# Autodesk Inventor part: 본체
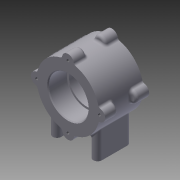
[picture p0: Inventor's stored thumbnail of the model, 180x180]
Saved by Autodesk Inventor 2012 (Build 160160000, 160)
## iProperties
Created: 2015-03
Part Number: 본체
Material: 알루미늄-6061
Document SubType Name: Modeling
Designer: Owner
Density: 2.71 g/cm^3
Mass: 450.772 g
Surface Area: 332.692 cm^2
Volume: 166.337 cm^3
Author: Owner
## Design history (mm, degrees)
sketch "스케치1"
  geometry: C1 r 37 at (0, 0); 1 further point
  constraints: 1 centre point, 1 coincident
  dimensions: "d0" = 74 diameter of C1
extrude "돌출1" new body sketch "스케치1" stored distance "d1" = 52; taper "d2" = 0 deg
sketch "스케치2"
  geometry: L1 (-37, 26)-(37, 26) reference; L2 (37, -26)-(-37, -26) reference; L3 (37, -26)-(37, 26) reference; L4 (-37, -26)-(-37, 26) reference; L5 (0, 26)-(0, -26); L6 (23.5, 26)-(23.5, 4); L7 (23.5, 4)-(21, 4); L8 (21, 4)-(21, -4); L9 (21, -4)-(23.5, -4); L10 (23.5, -4)-(23.5, -26); 2 further points
  constraints: 12 end point, 4 parallel, 3 midpoint, 2 collinear, 2 point on line, 1 coincident, 1 perpendicular, 1 vertical alignment
  dimensions: "d3" = 22 distance of L6.start L6.end; "d4" = 47 diameter of L6 L5; "d5" = 42 diameter of L8 L5
revolve "회전1" sketch "스케치2" stored, may be unused: angle "d6" = 90 deg
sketch "스케치3"
  geometry: C1 r 23.5 at (0, 0) reference; A1 r 37 centre (0, 0) between (-37, 0) and (-36.338, 6.969) reference; A2 r 7 centre (-37, 0) between (-36.338, 6.969) and (-36.338, -6.969)
  constraints: 5 point on circle, 1 centre point, 1 horizontal alignment
  dimensions: "d7" = 7 radius of A2
extrude "돌출2" join sketch "스케치3" distance "d8" = 15; taper "d9" = 0 deg
sketch "스케치4"
  geometry: C1 r 23.5 at (0, 0) reference; 1 further point
  constraints: 1 vertical alignment
  dimensions: "d13" = 37 distance of C1.centre point (0, 37)
hole "구멍1" sketch "스케치4" at (0, 37) diameter "d14" = 3.242; stored, may be unused: countersink angle "d18" = 90 deg, drill point angle "d20" = 118 deg; dims "d15" = 8, "d16" = 4, "d17" = 2, "d19" = 11
node "작업 평면1"
node "작업 평면2"
sketch "스케치5"
  geometry: L1 (19, 15)-(19, -15); L2 (29, -15)-(29, 15); A1 r 5 centre (24, -15) between (19, -15) and (29, -15); A2 r 5 centre (24, 15) between (29, 15) and (19, 15); 2 further points
  constraints: 4 end point, 4 point on circle, 4 tangent, 2 centre point, 1 horizontal alignment, 1 midpoint, 1 parallel, 1 vertical
  dimensions: "d25" = 40 dimension on A1 A2; "d26" = 24 horizontal distance of A1.centre point (0, 0); "d27" = 5 radius of A2
extrude "돌출3" join sketch "스케치5" stored distance "d28" = 15; taper "d29" = 0 deg
sketch "스케치6"
  geometry: A1 r 5 centre (24, -15) between (19, -15) and (29, -15) reference; A2 r 5 centre (24, 15) between (29, 15) and (19, 15) reference; 3 further points
  constraints: 2 coincident
hole "구멍2" sketch "스케치6" at (24, 15), (24, -15) diameter "d30" = 4.134; stored, may be unused: countersink angle "d34" = 90 deg, drill point angle "d36" = 118 deg; dims "d31" = 6, "d32" = 4, "d33" = 2, "d35" = 8
node "작업 평면4"
  node "작업 평면3"
sketch "스케치7"
  geometry: 2 further points
  constraints: 1 coincident, 1 other
feature "엠보싱1" sketch "스케치7" dims "d39" = 0.5, "d40" = 0
chamfer "모따기1" distance "d41" = 1; stored, may be unused: second distance "d42" = 2, angle "d43" = 45 deg
fillet "모깎기1" dims "d44" = 3
fillet "모깎기2" dims "d45" = 3
fillet "모깎기3" dims "d46" = 3
node "작업 평면5"
fillet "모깎기4" dims "d47" = 0.3
fillet "모깎기5" dims "d48" = 3
fillet "모깎기6" dims "d49" = 3
node "솔리드1"
pattern_circular "원형 패턴1" dims angle "d11" = 360 deg
pattern_circular "원형 패턴2" dims angle "d22" = 360 deg
mirror "대칭1"
mirror "대칭2"
mirror "대칭3"
mirror "대칭4"
mirror "대칭5"
mirror "대칭6"
other parameters: "d24" = -56, "d37" = -45 deg
